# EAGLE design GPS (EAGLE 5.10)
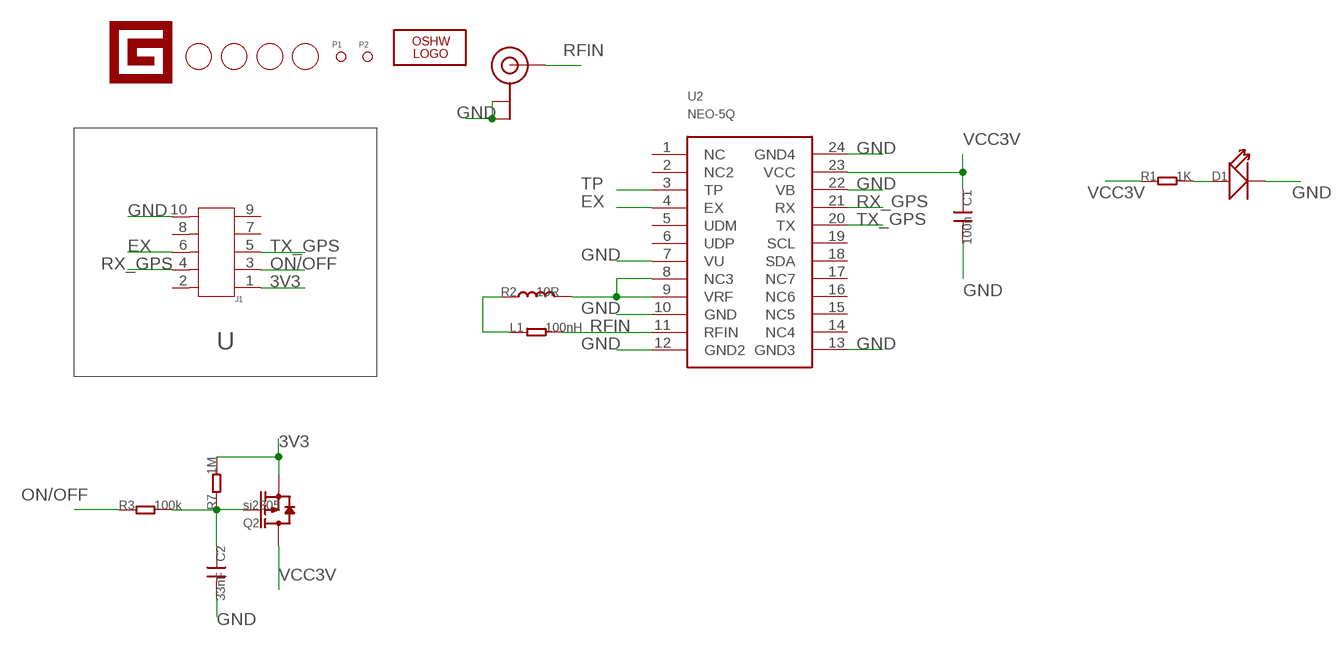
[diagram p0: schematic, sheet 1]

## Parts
C1  100n  C-0603  [0603]
C2  33nF  C-0603  [0603]
D1  LED-0603  [D0603]
J1  HEADER-SHF-105-01-L-D-SM  [SHF-105-01-L-D-SM]
J2  U.FL  [U.FL]
L1  100nH  R-0603  [0603]
LOGO1  LOGO-OSHW-FILLX0150-NT  [OSHW_FILLX150_NOTEXT]
P1  PAD-MARK  [ROUND-MARK-0.635]
P2  PAD-MARK  [ROUND-MARK-0.635]
Q2  si2305  MOSFET-P-SOT23  [SOT23]
R1  1K  R-0603  [0603]
R2  10R  L0603  [0603]
R3  100k  005-R0603_S  [0603_S]
R7  1M  005-R0603_S  [0603_S]
U2  NEO-5Q  [NEO-5Q]
U$1  LOGO-GADGETEER-NORMAL  [GADGETEER-SILK]
U$2  PAD-HOLE'3.2/7.0'  [HOLE-D-3.2/7.0]
U$3  PAD-HOLE'3.2/7.0'  [HOLE-D-3.2/7.0]
U$4  PAD-HOLE'3.2/7.0'  [HOLE-D-3.2/7.0]
U$5  PAD-HOLE'3.2/7.0'  [HOLE-D-3.2/7.0]

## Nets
3V3: J1.1 Q2.2(S) R7.2
EX: J1.6 U2.4(EX)
GND: C1.2 C2.2 D1.- J1.10 J2.P$1(GND) J2.P$2(GND) U2.7(VU) U2.10(GND) U2.12(GND2) U2.13(GND3) U2.22(VB) U2.24(GND4)
N$1: D1.+ R1.2
N$2: L1.1 R2.1
N$3: C2.1 Q2.1(G) R3.2 R7.1
N$8: R2.2 U2.8(NC3) U2.9(VRF)
ON/OFF: J1.3 R3.1
RFIN: J2.P$3(SIGNAL) L1.2 U2.11(RFIN)
RX_GPS: J1.4 U2.21(RX)
TP: U2.3(TP)
TX_GPS: J1.5 U2.20(TX)
VCC3V: C1.1 Q2.3(D) R1.1 U2.23(VCC)
Unconnected: J1.2 J1.7 J1.8 J1.9 U2.1(NC) U2.2(NC2) U2.5(UDM) U2.6(UDP) U2.14(NC4) U2.15(NC5) U2.16(NC6) U2.17(NC7) U2.18(SDA) U2.19(SCL)

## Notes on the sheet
- U

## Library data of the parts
C1 C2 = Discrete:C*: Ceramic Capacitors
D1 = Discrete:LED*
J1 = Connector:HEADER-SHF-105-01-L-D-SM
J2 = SparkFun2:U.FL
L1 R1 = Discrete:R*
LOGO1 = Logo:LOGO-OSHW-FILL
P1 P2 = Discreter:PAD-MARK
Q2 = Discrete:MOSFET-P: Si2305DS Si2323CDS
R2 = Discrete:L*
R3 R7 = Discrete:005-R*
U2 = Seeed:NEO-5Q
U$1 = Logo:LOGO-GADGETEER
U$2-U$5 = Discreter:PAD-HOLE

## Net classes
0 default: width 0.203 mm, drill 0.305 mm, clearance 0.203 mm

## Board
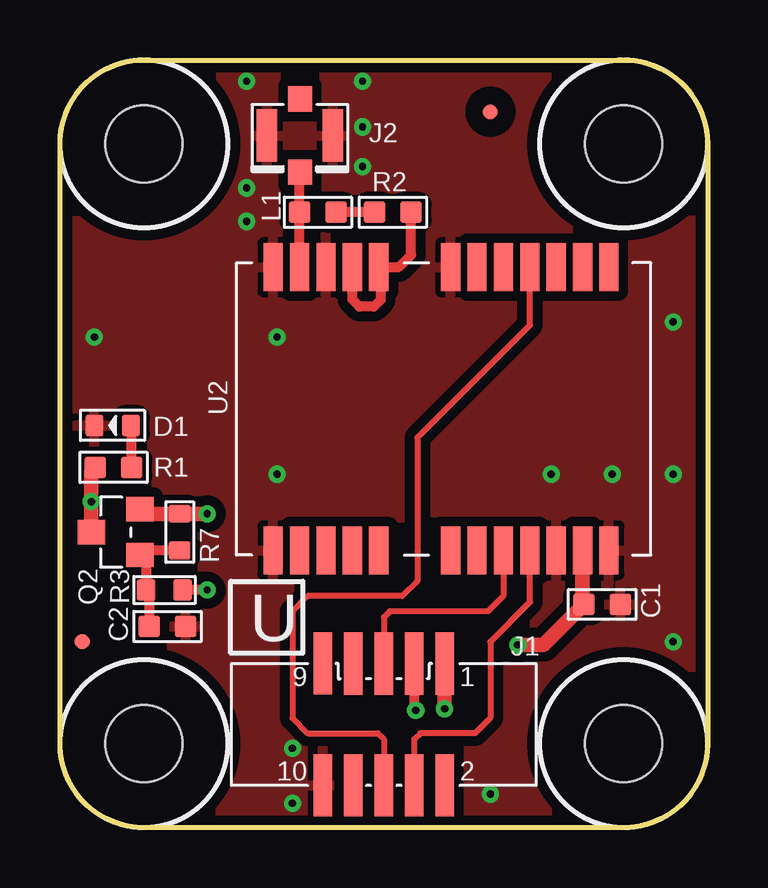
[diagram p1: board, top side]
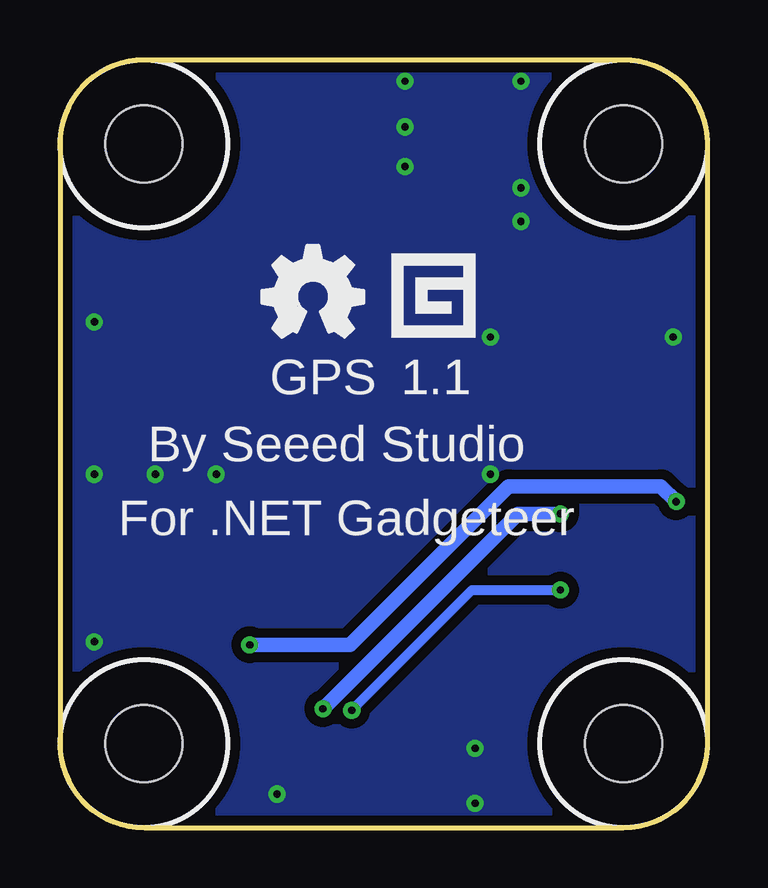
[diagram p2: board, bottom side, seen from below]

Size 27 x 32 mm. Coordinates in mm from the lower left corner, seen from the top.
Outline: 0,28.5 arc-90 3.5,32 23.5,32 arc-90 27,28.5 27,3.5 arc-90 23.5,0 3.5,0 arc-90 0,3.5 0,28.5
Copper layers (1*16): Top 0.035mm / dielectric 1.5mm / Bottom 0.035mm
Design rules "default *": minimum track width 10mil, minimum drill 12mil, track to track 8mil, track to pad 8mil, pad to pad 8mil, via to via 8mil, smd to smd 8mil, copper to edge 10mil, drill to drill 8mil, minimum pad ring 10mil, minimum via ring 8mil, stop-mask expansion 4mil, vias tented up to drill 100mil, thermal gap 10mil

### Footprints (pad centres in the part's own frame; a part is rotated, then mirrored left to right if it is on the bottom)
0603 = smd 0.889 x 0.889: 1 -0.762,0; 2 0.762,0
D0603 = smd 0.762 x 0.889: + -0.762,0; - 0.762,0
SHF-105-01-L-D-SM = smd 0.762 x 2.6: 1 -2.54,-2.54; 2 -2.54,2.54; 3 -1.27,-2.54; 4 -1.27,2.54; 5 0,-2.54; 6 0,2.54; 7 1.27,-2.54; 8 1.27,2.54; 9 2.54,-2.546; 10 2.54,2.54
U.FL = smd 2.2 x 0.85: P$1 0,1.375; P$2 0,-1.375 | smd 1.05 x 1: P$3 1.525,0; P$4 -1.525,0
ROUND-MARK-0.635 = smd 0.635 x 0.635: P$1 0,0
SOT23 = smd 1.016 x 1.143: 1 -0.95,-1.016; 2 0.95,-1.016; 3 0,1.016
0603_S = smd 0.762 x 0.889: 1 -0.762,0; 2 0.762,0
NEO-5Q = smd 2 x 0.8: 1 12,-14; 2 12,-12.9; 3 12,-11.8; 4 12,-10.7; 5 12,-9.6; 6 12,-8.5; 7 12,-7.4; 8 12,-4.4; 9 12,-3.3; 10 12,-2.2; 11 12,-1.1; 12 12,0; 13 0.2,0; 14 0.2,-1.1; 15 0.2,-2.2; 16 0.2,-3.3; 17 0.2,-4.4; 18 0.2,-7.4; 19 0.2,-8.5; 20 0.2,-9.6; 21 0.2,-10.7; 22 0.2,-11.8; 23 0.2,-12.9; 24 0.2,-14
HOLE-D-3.2/7.0 = hole 3.2: 0,0

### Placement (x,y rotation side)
C1  22.6,9.3 0 top
C2  4.48,8.38 0 top
D1  2.2,16.76 180 top
J1  13.5,4.3 180 top
J2  10.01,28.85 270 top
L1  10.76,25.65 180 top
LOGO1  18.58,20.45 0 bottom
P1  0.93,7.74 270 top
P2  17.95,29.84 270 top
Q2  2.32,12.32 90 top
R1  2.24,15.02 0 top
R2  13.88,25.65 0 top
R3  4.36,9.9 180 top
R7  4.99,12.32 90 top
U2  8.89,11.36 90 top
U$1  11.02,22.6 0 bottom
U$2  23.5,28.5 270 top
U$3  23.5,3.5 270 top
U$4  3.5,28.5 270 top
U$5  3.5,3.5 270 top

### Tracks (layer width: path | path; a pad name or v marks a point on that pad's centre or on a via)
3V3  (via drill 0.3)
  Top 0.61: J1.1 v16.04,4.95 | v6.13,13.08 R7.2 3.53,13.08 Q2.2
  Bottom 0.61: v16.04,4.95 7.91,13.08 v6.13,13.08
EX
  Top 0.254: U2.4 19.6,20.95 14.9,16.25 14.9,10.29 14.26,9.65 10.32,9.65 9.69,9.02 9.69,4.57 10.32,3.94 13.25,3.94 13.5,3.68 J1.6
GND  (via drill 0.3 pad 0.64)
  other vias: 9.69,1.01 17.95,1.39 9.69,3.3 9.05,14.73 9.05,20.45 1.44,20.45 25.56,21.08 25.56,14.73 20.48,14.73 23.02,14.73 25.56,7.74 7.79,31.11 7.79,26.67 7.79,25.27 12.61,31.11 12.61,29.21 12.61,27.56
  pour Top (isolate 0.406): 27.47,32.51 27.47,-0.51 -0.47,-0.51 -0.47,32.51
  pour Bottom (isolate 0.406): 27.47,32.51 27.47,-0.51 -0.47,-0.51 -0.47,32.51
N$1
  Top 0.406: D1.+ 2.96,15.06 R1.2
N$2
  Top 0.406: R2.1 L1.1
N$3
  Top 0.406: 3.59,11.37 Q2.1 | 3.59,11.37 R3.2 3.72,9.9 C2.1 | R7.1 3.59,11.55 3.59,11.37
N$8
  Top 0.406: U2.9 12.19,22.01 12.48,21.71 13.09,21.71 13.37,22 13.37,23.27 U2.8 14.13,23.37 14.64,23.87 R2.2
ON/OFF  (via drill 0.3)
  Top 0.406: v6.13,9.9 R3.1 | J1.3 14.77,4.95 v14.83,4.89
  Bottom 0.406: v6.13,9.9 9.82,9.9 v14.83,4.89
RFIN
  Top 0.406: U2.11 L1.2 10,27.32 J2.P$3
RX_GPS
  Top 0.254: U2.21 19.6,9.4 17.95,7.74 17.95,4.57 17.31,3.94 15.02,3.94 14.77,3.68 J1.4
TX_GPS
  Top 0.254: J1.5 13.5,8.76 13.75,9.02 17.85,9.02 18.49,9.65 U2.20
VCC3V  (via drill 0.3)
  Top 0.61: U2.23 21.79,9.36 C1.1 20.16,7.62 v19.09,7.62 | Q2.3 v1.31,13.59 1.31,14.85 R1.1
  Bottom 0.61: v19.09,7.62 14.9,7.62 8.29,14.22 1.94,14.22 v1.31,13.59

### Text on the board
tPlace: J2 | U
bPlace: 1.1 | GPS | By Seeed Studio | For .NET Gadgeteer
